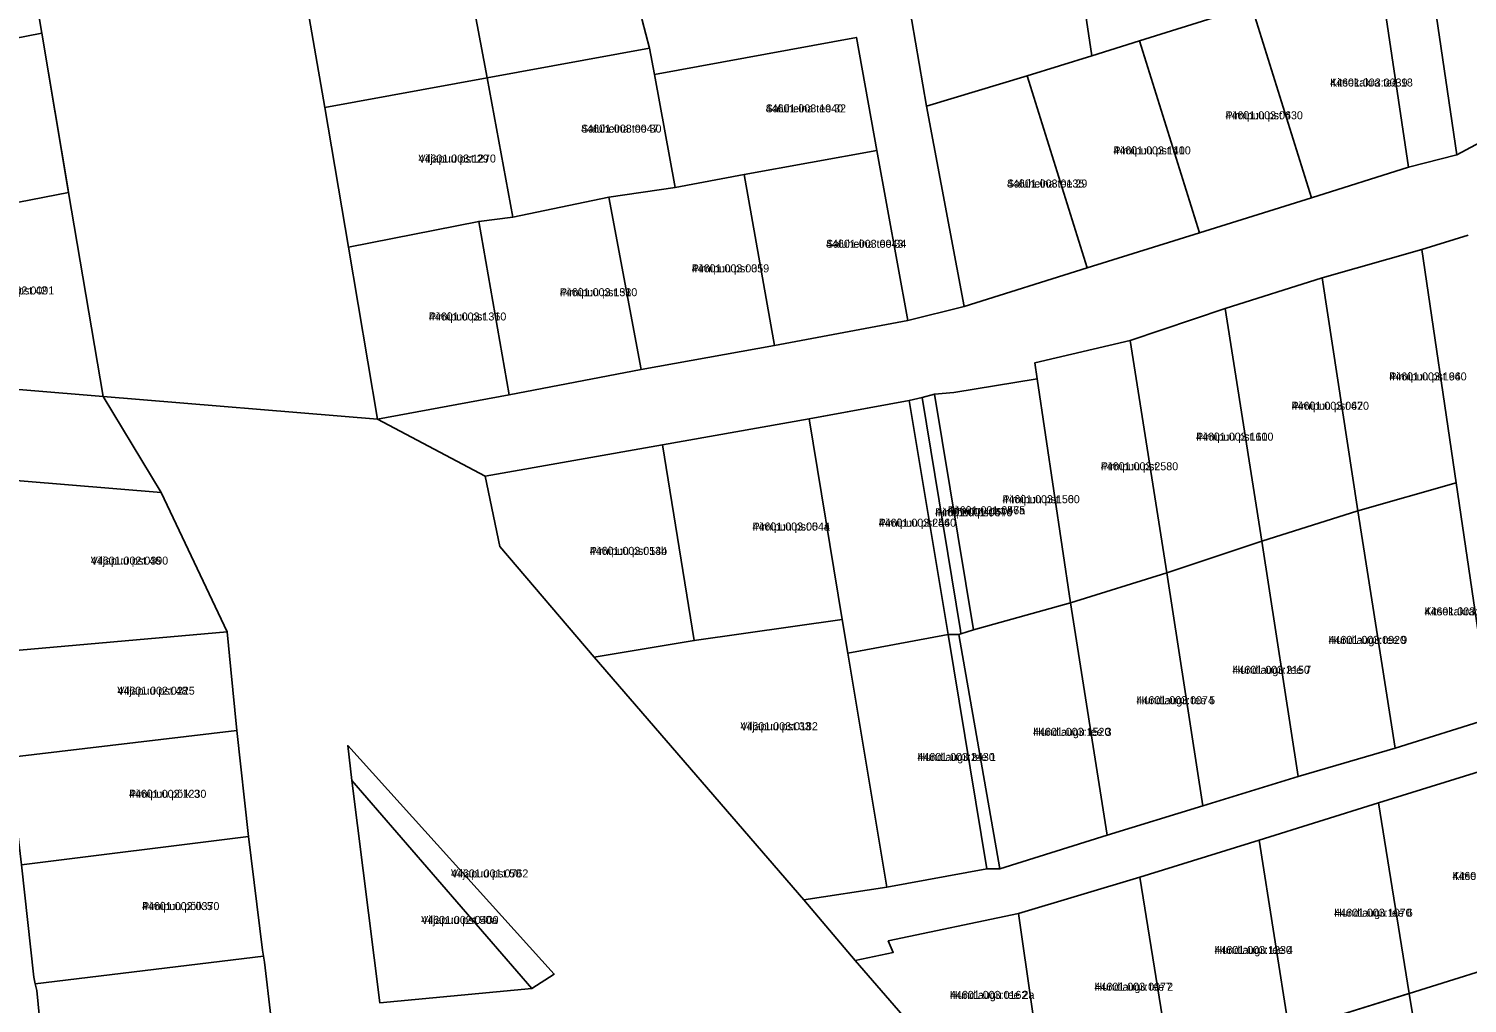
# Model space of a CAD drawing. Extents: x 551843 to 558501, y 6589003 to 6595718.
# Drawn here: x 553189.3 to 553458.8, y 6593469.6 to 6593652.3 of the extents above; entities that cross this region are included whole.
import ezdxf

# ---------------------------------------------------------------- set-up
doc = ezdxf.new("R2010")
doc.units = 0
for name, color, linetype in [('L_AADRESS', 7, 'Continuous'), ('PIIR', 7, 'Continuous'), ('TUNNUS', 7, 'Continuous')]:
    doc.layers.add(name, color=color, linetype=linetype)

msp = doc.modelspace()

# ---------------------------------------------------------------- linework, layer by layer
at = {"layer": 'PIIR'}
for points in [[(553186.23, 6593983.27), (553193.49, 6593939.32), (553196.91, 6593918.08), (553200.54, 6593897.24), (553204.15, 6593876.28), (553210.71, 6593836.66), (553212.49, 6593828.12), (553215.73, 6593808.36), (553218.98, 6593788.61), (553222.26, 6593768.87), (553225.56, 6593749.13), (553229, 6593729.26), (553232.23, 6593710.23), (553234.24, 6593699.21), (553240.17, 6593664.09), (553244.79, 6593637.48), (553249.21, 6593611.32), (553254.67, 6593579.06), (553203.23, 6593583.33), (553196.77, 6593621.59), (553191.73, 6593651.42), (553186.62, 6593681.71)], [(553352.71, 6593665.77), (553357.52, 6593637.75), (553364.55, 6593600.22), (553354, 6593597.58), (553348.22, 6593629.46), (553344.38, 6593650.63), (553306.53, 6593643.69), (553305.63, 6593648.61), (553304.26, 6593653.85)], [(553451.6, 6593664.73), (553456.92, 6593628.62), (553447.86, 6593626.29), (553442.22, 6593664.03)], [(553459.03, 6593613.56), (553450.33, 6593610.86), (553431.68, 6593605.55), (553413.49, 6593599.83), (553395.68, 6593593.86), (553377.83, 6593589.66), (553378.23, 6593586.67), (553362.63, 6593584.06), (553358.99, 6593583.76), (553356.69, 6593583.15), (553354.28, 6593582.6), (553335.54, 6593579.16), (553308.07, 6593574.28), (553274.83, 6593568.41), (553254.67, 6593579.06), (553279.34, 6593583.66), (553304.03, 6593588.37), (553329.06, 6593592.9), (553354, 6593597.58), (553364.55, 6593600.22), (553387.65, 6593607.43), (553408.67, 6593614.02), (553429.68, 6593620.59), (553447.86, 6593626.29), (553456.92, 6593628.62), (553484.19, 6593643.24)], [(553464.6, 6593514.12), (553442.23, 6593507.16), (553419.86, 6593500.2), (553397.49, 6593493.23), (553374.78, 6593486.42), (553350.34, 6593481.31), (553351.3, 6593479.15), (553344.14, 6593477.66), (553334.55, 6593488.98), (553350.06, 6593491.36), (553368.83, 6593494.8), (553371.25, 6593494.81), (553391.39, 6593501.13), (553409.27, 6593506.63), (553427.18, 6593512.11), (553445.36, 6593517.44), (553463.29, 6593523.02), (553456.77, 6593567.16), (553450.33, 6593610.86), (553459.03, 6593613.56)], [(553161.75, 6593586.77), (553203.23, 6593583.33), (553214.13, 6593565.37), (553179.35, 6593568.24)], [(553235.86, 6593457.11), (553233.47, 6593477.32), (553233.28, 6593478.43), (553233.08, 6593479.55), (553230.48, 6593500.89), (553228.29, 6593520.73), (553227.15, 6593532.15), (553226.5, 6593539.24), (553214.13, 6593565.37), (553203.23, 6593583.33), (553254.67, 6593579.06), (553274.83, 6593568.41), (553277.57, 6593555.25), (553295.26, 6593534.46), (553334.55, 6593488.98), (553344.14, 6593477.66), (553370.14, 6593447.65)], [(553187.95, 6593495.54), (553190.23, 6593474.54), (553190.51, 6593473.27), (553190.79, 6593472), (553192.74, 6593452.2), (553183, 6593451.01)]]:
    msp.add_lwpolyline(points, dxfattribs=at)
for points in [[(553393.84, 6593682.83), (553408.79, 6593684.81), (553413.24, 6593654.95), (553397.41, 6593649.99), (553388.52, 6593647.21), (553385.14, 6593669.82), (553383.4, 6593681.45)], [(553158.12, 6593675.89), (553186.62, 6593681.71), (553191.73, 6593651.42), (553152.34, 6593643.76), (553147.42, 6593673.71)], [(553270.23, 6593669.6), (553287.6, 6593672.78), (553300.33, 6593675.29), (553304.26, 6593653.85), (553305.63, 6593648.61), (553275.22, 6593643.04)], [(553456.92, 6593628.62), (553451.6, 6593664.73), (553467.99, 6593673.52), (553484.19, 6593643.24)], [(553240.17, 6593664.09), (553263.58, 6593668.38), (553270.23, 6593669.6), (553275.22, 6593643.04), (553244.79, 6593637.48)], [(553352.71, 6593665.77), (553385.14, 6593669.82), (553388.52, 6593647.21), (553376.39, 6593643.42), (553357.52, 6593637.75)], [(553442.22, 6593664.03), (553447.86, 6593626.29), (553429.68, 6593620.59), (553418.42, 6593656.57)], [(553408.67, 6593614.02), (553397.41, 6593649.99), (553413.24, 6593654.95), (553418.42, 6593656.57), (553429.68, 6593620.59)], [(553191.73, 6593651.42), (553196.62, 6593622.46), (553196.77, 6593621.59), (553157.24, 6593613.91), (553152.34, 6593643.76)], [(553348.22, 6593629.46), (553323.38, 6593624.91), (553310.4, 6593622.53), (553306.53, 6593643.69), (553344.38, 6593650.63)], [(553305.63, 6593648.61), (553306.53, 6593643.69), (553310.4, 6593622.53), (553298, 6593620.69), (553279.99, 6593616.96), (553275.22, 6593643.04)], [(553387.65, 6593607.43), (553376.39, 6593643.42), (553388.52, 6593647.21), (553397.41, 6593649.99), (553408.67, 6593614.02)], [(553244.79, 6593637.48), (553275.22, 6593643.04), (553279.99, 6593616.96), (553273.61, 6593616.16), (553249.21, 6593611.32)], [(553376.39, 6593643.42), (553387.65, 6593607.43), (553364.55, 6593600.22), (553357.52, 6593637.75)], [(553354, 6593597.58), (553329.06, 6593592.9), (553323.38, 6593624.91), (553348.22, 6593629.46)], [(553304.03, 6593588.37), (553298, 6593620.69), (553310.4, 6593622.53), (553323.38, 6593624.91), (553329.06, 6593592.9)], [(553196.77, 6593621.59), (553203.23, 6593583.33), (553161.75, 6593586.77), (553157.24, 6593613.91)], [(553298, 6593620.69), (553304.03, 6593588.37), (553279.34, 6593583.66), (553273.61, 6593616.16), (553279.99, 6593616.96)], [(553254.67, 6593579.06), (553249.21, 6593611.32), (553273.61, 6593616.16), (553279.34, 6593583.66)], [(553431.68, 6593605.55), (553450.33, 6593610.86), (553456.77, 6593567.16), (553438.37, 6593561.92)], [(553431.68, 6593605.55), (553438.37, 6593561.92), (553420.37, 6593556.2), (553413.49, 6593599.83)], [(553395.68, 6593593.86), (553413.49, 6593599.83), (553420.37, 6593556.2), (553402.54, 6593550.3)], [(553378.23, 6593586.67), (553377.83, 6593589.66), (553395.68, 6593593.86), (553402.54, 6593550.3), (553384.47, 6593544.67)], [(553358.99, 6593583.76), (553362.63, 6593584.06), (553378.23, 6593586.67), (553384.47, 6593544.67), (553366.31, 6593539.59)], [(553361.57, 6593538.7), (553354.28, 6593582.6), (553356.69, 6593583.15), (553363.88, 6593539.48), (553363.97, 6593538.88), (553363.56, 6593538.72)], [(553363.88, 6593539.48), (553356.69, 6593583.15), (553358.99, 6593583.76), (553366.31, 6593539.59), (553363.97, 6593538.88)], [(553337.88, 6593579.59), (553354.28, 6593582.6), (553361.57, 6593538.7), (553345.14, 6593535.69), (553342.8, 6593535.26), (553341.74, 6593541.57), (553335.54, 6593579.16)], [(553335.54, 6593579.16), (553341.74, 6593541.57), (553313.99, 6593537.6), (553308.07, 6593574.28)], [(553274.83, 6593568.41), (553308.07, 6593574.28), (553313.99, 6593537.6), (553295.26, 6593534.46), (553277.57, 6593555.25)], [(553214.13, 6593565.37), (553226.5, 6593539.24), (553183.24, 6593535.42), (553179.35, 6593568.24)], [(553438.37, 6593561.92), (553456.77, 6593567.16), (553463.29, 6593523.02), (553445.36, 6593517.44)], [(553420.37, 6593556.2), (553438.37, 6593561.92), (553445.36, 6593517.44), (553427.18, 6593512.11)], [(553420.37, 6593556.2), (553427.18, 6593512.11), (553409.27, 6593506.63), (553402.54, 6593550.3)], [(553402.54, 6593550.3), (553409.27, 6593506.63), (553391.39, 6593501.13), (553384.47, 6593544.67)], [(553384.47, 6593544.67), (553391.39, 6593501.13), (553371.25, 6593494.81), (553363.56, 6593538.72), (553363.97, 6593538.88), (553366.31, 6593539.59)], [(553295.26, 6593534.46), (553313.99, 6593537.6), (553341.74, 6593541.57), (553342.8, 6593535.26), (553350.06, 6593491.36), (553334.55, 6593488.98)], [(553183.24, 6593535.42), (553226.5, 6593539.24), (553227.15, 6593532.15), (553228.29, 6593520.73), (553185.59, 6593515.66)], [(553345.14, 6593535.69), (553361.57, 6593538.7), (553368.83, 6593494.8), (553350.06, 6593491.36), (553342.8, 6593535.26)], [(553185.59, 6593515.66), (553228.29, 6593520.73), (553230.48, 6593500.89), (553187.95, 6593495.54)], [(553249.06, 6593517.92), (553249.86, 6593511.36), (553255.08, 6593469.72), (553283.56, 6593472.38), (553287.76, 6593475.08)], [(553287.76, 6593475.08), (553283.56, 6593472.38), (553249.86, 6593511.36), (553249.06, 6593517.92)], [(553442.23, 6593507.16), (553464.6, 6593514.12), (553469.9, 6593478.3), (553447.97, 6593471.48)], [(553283.56, 6593472.38), (553255.08, 6593469.72), (553249.86, 6593511.36)], [(553419.86, 6593500.2), (553442.23, 6593507.16), (553447.97, 6593471.48), (553426.02, 6593464.66), (553425.46, 6593464.48)], [(553187.95, 6593495.54), (553230.48, 6593500.89), (553233.08, 6593479.55), (553233.28, 6593478.43), (553190.51, 6593473.27), (553190.23, 6593474.54)], [(553397.49, 6593493.23), (553419.86, 6593500.2), (553425.46, 6593464.48), (553404.1, 6593457.83), (553403.21, 6593457.55)], [(553374.78, 6593486.42), (553397.49, 6593493.23), (553403.21, 6593457.55), (553380.08, 6593450.56), (553379.68, 6593452.01)], [(553350.34, 6593481.31), (553374.78, 6593486.42), (553379.68, 6593452.01), (553370.14, 6593447.65), (553344.14, 6593477.66), (553351.3, 6593479.15)], [(553190.79, 6593472), (553190.51, 6593473.27), (553233.28, 6593478.43), (553233.47, 6593477.32), (553235.86, 6593457.11), (553227.93, 6593456.17), (553226.32, 6593456.06), (553192.74, 6593452.2)], [(553447.97, 6593471.48), (553469.9, 6593478.3), (553475.35, 6593441.4), (553454.04, 6593434.77)], [(553447.97, 6593471.48), (553454.04, 6593434.77), (553456.47, 6593420.04), (553435.28, 6593414.24), (553426.02, 6593464.66), (553447.68, 6593471.39)]]:
    msp.add_lwpolyline(points, close=True, dxfattribs=at)

# ---------------------------------------------------------------- texts
at = {"layer": 'L_AADRESS'}
for s, p in [('Kitsekakra tee 18', (553433.14, 6593641.43)), ('Saluheina tee 32', (553327.38, 6593636.58)), ('Pirnipuu pst 43', (553413.54, 6593635.29)), ('Saluheina tee 30', (553292.81, 6593632.79)), ('Viljapuu pst 29', (553262.33, 6593627.18)), ('Pirnipuu pst 41', (553392.53, 6593628.71)), ('Saluheina tee 29', (553372.59, 6593622.5)), ('Saluheina tee 34', (553338.69, 6593611.21)), ('Pirnipuu pst 35', (553313.53, 6593606.6)), ('Viljapuu pst 42', (553179.57, 6593602.46)), ('Pirnipuu pst 33', (553288.82, 6593602.13)), ('Pirnipuu pst 31', (553264.28, 6593597.58)), ('Pirnipuu pst 64', (553444.23, 6593586.35)), ('Pirnipuu pst 62', (553425.93, 6593580.85)), ('Pirnipuu pst 60', (553408.02, 6593575.06)), ('Pirnipuu pst 58', (553390.18, 6593569.51)), ('Pirnipuu pst 56', (553371.73, 6593563.34)), ('Pirnipuu pst 54c', (553359.12, 6593560.89)), ('Pirnipuu pst 56a', (553361.5, 6593561.27)), ('Pirnipuu pst 54a', (553324.91, 6593558.22)), ('Pirnipuu pst 54', (553348.55, 6593558.93)), ('Viljapuu pst 46', (553200.92, 6593551.83)), ('Pirnipuu pst 54b', (553294.41, 6593553.66)), ('Kitsekakra tee 22', (553450.83, 6593542.31)), ('Hundiaugu tee 9', (553432.86, 6593536.97)), ('Hundiaugu tee 7', (553414.86, 6593531.36)), ('Viljapuu pst 48', (553205.9, 6593527.45)), ('Hundiaugu tee 5', (553396.87, 6593525.67)), ('Viljapuu pst 33', (553322.66, 6593520.79)), ('Hundiaugu tee 3', (553377.48, 6593519.74)), ('Hundiaugu tee 1', (553355.81, 6593515.03)), ('Pirnipuu põik 3', (553208.08, 6593508.13)), ('Viljapuu pst 50', (553268.41, 6593493.2)), ('Kitsekakra tee 24', (553456.06, 6593492.73)), ('Pirnipuu põik 5', (553210.52, 6593487.08)), ('Viljapuu pst 50a', (553262.83, 6593484.49)), ('Hundiaugu tee 6', (553433.91, 6593485.84)), ('Hundiaugu tee 4', (553411.48, 6593478.86)), ('Hundiaugu tee 2', (553389, 6593471.97)), ('Hundiaugu tee 2a', (553361.91, 6593470.44))]:
    msp.add_text(s, height=1.5, dxfattribs=at).set_placement(p)
at = {"layer": 'TUNNUS'}
for s, p in [('44601:003:0039', (553433.14, 6593641.43)), ('44601:003:1040', (553327.38, 6593636.58)), ('44601:003:0630', (553413.54, 6593635.29)), ('44601:003:0047', (553292.81, 6593632.79)), ('44601:003:1100', (553392.53, 6593628.71)), ('44601:003:1270', (553262.33, 6593627.18)), ('44601:003:0135', (553372.59, 6593622.5)), ('44601:003:0043', (553338.69, 6593611.21)), ('44601:003:0059', (553313.53, 6593606.6)), ('44601:002:0091', (553179.57, 6593602.46)), ('44601:003:1510', (553288.82, 6593602.13)), ('44601:003:1360', (553264.28, 6593597.58)), ('44601:003:1960', (553444.23, 6593586.35)), ('44601:003:0470', (553425.93, 6593580.85)), ('44601:003:1110', (553408.02, 6593575.06)), ('44601:003:2530', (553390.18, 6593569.51)), ('44601:003:1500', (553371.73, 6593563.34)), ('44601:001:0476', (553359.12, 6593560.89)), ('44601:001:0475', (553361.5, 6593561.27)), ('44601:003:0044', (553324.91, 6593558.22)), ('44601:003:2460', (553348.55, 6593558.93)), ('44601:002:0390', (553200.92, 6593551.83)), ('44601:003:0134', (553294.41, 6593553.66)), ('44601:003:1380', (553450.83, 6593542.31)), ('44601:003:0920', (553432.86, 6593536.97)), ('44601:003:2150', (553414.86, 6593531.36)), ('44601:002:0225', (553205.9, 6593527.45)), ('44601:003:0074', (553396.87, 6593525.67)), ('44601:003:0182', (553322.66, 6593520.79)), ('44601:003:1520', (553377.48, 6593519.74)), ('44601:003:2430', (553355.81, 6593515.03)), ('44601:002:1230', (553208.08, 6593508.13)), ('44601:001:0762', (553268.41, 6593493.2)), ('44601:003:1880', (553456.06, 6593492.73)), ('44601:002:0370', (553210.52, 6593487.08)), ('44601:002:0400', (553262.83, 6593484.49)), ('44601:003:1070', (553433.91, 6593485.84)), ('44601:003:1230', (553411.48, 6593478.86)), ('44601:003:0077', (553389, 6593471.97)), ('44601:003:0162', (553361.91, 6593470.44))]:
    msp.add_text(s, height=1.5, dxfattribs=at).set_placement(p)

doc.saveas('drawing.dxf')
